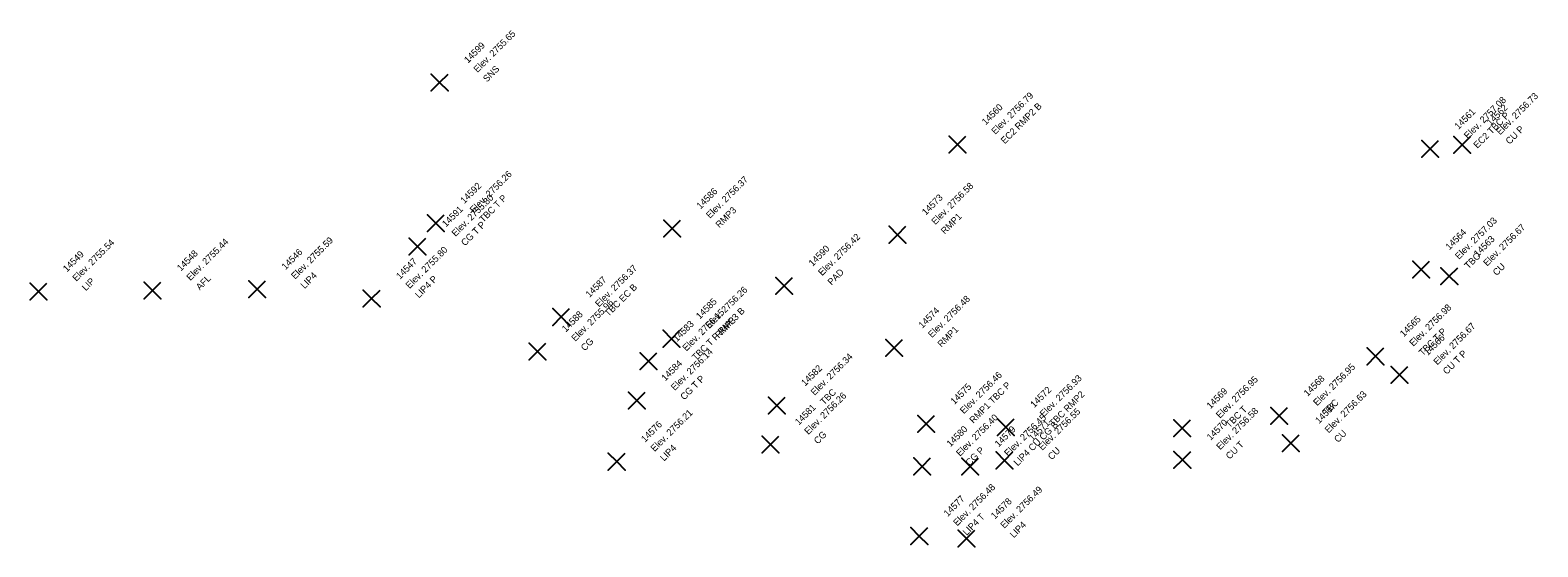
# Model space of a CAD drawing. Extents: x 2493999 to 2503109, y 700767 to 706646.
# Drawn here: x 2502322.65 to 2502349.68, y 703555.99 to 703565.25 of the extents above; entities that cross this region are included whole.
import ezdxf

# ---------------------------------------------------------------- set-up
doc = ezdxf.new("R2010")
doc.units = 0
doc.layers.add('ALG_CL_BLUE_Horiz', color=7, linetype='Continuous')
doc.layers.add('DES_SURFACE_Existing-Ground', color=7, linetype='Continuous')

msp = doc.modelspace()

# ---------------------------------------------------------------- linework, layer by layer
at = {"layer": 'ALG_CL_BLUE_Horiz'}
for points in [[(2502329.994, 703564.309), (2502329.844, 703564.459), (2502329.994, 703564.309), (2502329.844, 703564.159), (2502329.994, 703564.309), (2502330.144, 703564.159), (2502329.994, 703564.309), (2502330.144, 703564.459)], [(2502339.277, 703563.201), (2502339.127, 703563.351), (2502339.277, 703563.201), (2502339.127, 703563.051), (2502339.277, 703563.201), (2502339.427, 703563.051), (2502339.277, 703563.201), (2502339.427, 703563.351)], [(2502347.752, 703563.12), (2502347.602, 703563.27), (2502347.752, 703563.12), (2502347.602, 703562.97), (2502347.752, 703563.12), (2502347.902, 703562.97), (2502347.752, 703563.12), (2502347.902, 703563.27)], [(2502348.328, 703563.192), (2502348.178, 703563.342), (2502348.328, 703563.192), (2502348.178, 703563.042), (2502348.328, 703563.192), (2502348.478, 703563.042), (2502348.328, 703563.192), (2502348.478, 703563.342)], [(2502329.927, 703561.791), (2502329.777, 703561.941), (2502329.927, 703561.791), (2502329.777, 703561.641), (2502329.927, 703561.791), (2502330.077, 703561.641), (2502329.927, 703561.791), (2502330.077, 703561.941)], [(2502334.162, 703561.694), (2502334.012, 703561.844), (2502334.162, 703561.694), (2502334.012, 703561.544), (2502334.162, 703561.694), (2502334.312, 703561.544), (2502334.162, 703561.694), (2502334.312, 703561.844)], [(2502338.202, 703561.582), (2502338.052, 703561.732), (2502338.202, 703561.582), (2502338.052, 703561.432), (2502338.202, 703561.582), (2502338.352, 703561.432), (2502338.202, 703561.582), (2502338.352, 703561.732)], [(2502329.599, 703561.371), (2502329.449, 703561.521), (2502329.599, 703561.371), (2502329.449, 703561.221), (2502329.599, 703561.371), (2502329.749, 703561.221), (2502329.599, 703561.371), (2502329.749, 703561.521)], [(2502347.59, 703560.96), (2502347.44, 703561.11), (2502347.59, 703560.96), (2502347.44, 703560.81), (2502347.59, 703560.96), (2502347.74, 703560.81), (2502347.59, 703560.96), (2502347.74, 703561.11)], [(2502324.846, 703560.58), (2502324.696, 703560.73), (2502324.846, 703560.58), (2502324.696, 703560.43), (2502324.846, 703560.58), (2502324.996, 703560.43), (2502324.846, 703560.58), (2502324.996, 703560.73)], [(2502326.723, 703560.605), (2502326.573, 703560.755), (2502326.723, 703560.605), (2502326.573, 703560.455), (2502326.723, 703560.605), (2502326.873, 703560.455), (2502326.723, 703560.605), (2502326.873, 703560.755)], [(2502336.172, 703560.667), (2502336.022, 703560.817), (2502336.172, 703560.667), (2502336.022, 703560.517), (2502336.172, 703560.667), (2502336.322, 703560.517), (2502336.172, 703560.667), (2502336.322, 703560.817)], [(2502348.097, 703560.838), (2502347.947, 703560.988), (2502348.097, 703560.838), (2502347.947, 703560.688), (2502348.097, 703560.838), (2502348.247, 703560.688), (2502348.097, 703560.838), (2502348.247, 703560.988)], [(2502322.802, 703560.566), (2502322.652, 703560.716), (2502322.802, 703560.566), (2502322.652, 703560.416), (2502322.802, 703560.566), (2502322.952, 703560.416), (2502322.802, 703560.566), (2502322.952, 703560.716)], [(2502328.775, 703560.436), (2502328.625, 703560.586), (2502328.775, 703560.436), (2502328.625, 703560.286), (2502328.775, 703560.436), (2502328.925, 703560.286), (2502328.775, 703560.436), (2502328.925, 703560.586)], [(2502332.173, 703560.107), (2502332.023, 703560.257), (2502332.173, 703560.107), (2502332.023, 703559.957), (2502332.173, 703560.107), (2502332.323, 703559.957), (2502332.173, 703560.107), (2502332.323, 703560.257)], [(2502334.151, 703559.718), (2502334.001, 703559.868), (2502334.151, 703559.718), (2502334.001, 703559.568), (2502334.151, 703559.718), (2502334.301, 703559.568), (2502334.151, 703559.718), (2502334.301, 703559.868)], [(2502338.142, 703559.556), (2502337.992, 703559.706), (2502338.142, 703559.556), (2502337.992, 703559.406), (2502338.142, 703559.556), (2502338.292, 703559.406), (2502338.142, 703559.556), (2502338.292, 703559.706)], [(2502331.747, 703559.489), (2502331.597, 703559.639), (2502331.747, 703559.489), (2502331.597, 703559.339), (2502331.747, 703559.489), (2502331.897, 703559.339), (2502331.747, 703559.489), (2502331.897, 703559.639)], [(2502333.739, 703559.316), (2502333.589, 703559.466), (2502333.739, 703559.316), (2502333.589, 703559.166), (2502333.739, 703559.316), (2502333.889, 703559.166), (2502333.739, 703559.316), (2502333.889, 703559.466)], [(2502346.772, 703559.402), (2502346.622, 703559.552), (2502346.772, 703559.402), (2502346.622, 703559.252), (2502346.772, 703559.402), (2502346.922, 703559.252), (2502346.772, 703559.402), (2502346.922, 703559.552)], [(2502347.203, 703559.068), (2502347.053, 703559.218), (2502347.203, 703559.068), (2502347.053, 703558.918), (2502347.203, 703559.068), (2502347.353, 703558.918), (2502347.203, 703559.068), (2502347.353, 703559.218)], [(2502333.531, 703558.61), (2502333.381, 703558.76), (2502333.531, 703558.61), (2502333.381, 703558.46), (2502333.531, 703558.61), (2502333.681, 703558.46), (2502333.531, 703558.61), (2502333.681, 703558.76)], [(2502336.038, 703558.521), (2502335.888, 703558.671), (2502336.038, 703558.521), (2502335.888, 703558.371), (2502336.038, 703558.521), (2502336.188, 703558.371), (2502336.038, 703558.521), (2502336.188, 703558.671)], [(2502338.715, 703558.191), (2502338.565, 703558.341), (2502338.715, 703558.191), (2502338.565, 703558.041), (2502338.715, 703558.191), (2502338.865, 703558.041), (2502338.715, 703558.191), (2502338.865, 703558.341)], [(2502345.048, 703558.336), (2502344.898, 703558.486), (2502345.048, 703558.336), (2502344.898, 703558.186), (2502345.048, 703558.336), (2502345.198, 703558.186), (2502345.048, 703558.336), (2502345.198, 703558.486)], [(2502340.146, 703558.134), (2502339.996, 703558.284), (2502340.146, 703558.134), (2502339.996, 703557.984), (2502340.146, 703558.134), (2502340.296, 703557.984), (2502340.146, 703558.134), (2502340.296, 703558.284)], [(2502343.305, 703558.112), (2502343.155, 703558.262), (2502343.305, 703558.112), (2502343.155, 703557.962), (2502343.305, 703558.112), (2502343.455, 703557.962), (2502343.305, 703558.112), (2502343.455, 703558.262)], [(2502335.925, 703557.82), (2502335.775, 703557.97), (2502335.925, 703557.82), (2502335.775, 703557.67), (2502335.925, 703557.82), (2502336.075, 703557.67), (2502335.925, 703557.82), (2502336.075, 703557.97)], [(2502345.253, 703557.847), (2502345.103, 703557.997), (2502345.253, 703557.847), (2502345.103, 703557.697), (2502345.253, 703557.847), (2502345.403, 703557.697), (2502345.253, 703557.847), (2502345.403, 703557.997)], [(2502333.168, 703557.514), (2502333.018, 703557.664), (2502333.168, 703557.514), (2502333.018, 703557.364), (2502333.168, 703557.514), (2502333.318, 703557.364), (2502333.168, 703557.514), (2502333.318, 703557.664)], [(2502338.645, 703557.43), (2502338.495, 703557.58), (2502338.645, 703557.43), (2502338.495, 703557.28), (2502338.645, 703557.43), (2502338.795, 703557.28), (2502338.645, 703557.43), (2502338.795, 703557.58)], [(2502339.508, 703557.428), (2502339.358, 703557.578), (2502339.508, 703557.428), (2502339.358, 703557.278), (2502339.508, 703557.428), (2502339.658, 703557.278), (2502339.508, 703557.428), (2502339.658, 703557.578)], [(2502340.12, 703557.537), (2502339.97, 703557.687), (2502340.12, 703557.537), (2502339.97, 703557.387), (2502340.12, 703557.537), (2502340.27, 703557.387), (2502340.12, 703557.537), (2502340.27, 703557.687)], [(2502343.31, 703557.547), (2502343.16, 703557.697), (2502343.31, 703557.547), (2502343.16, 703557.397), (2502343.31, 703557.547), (2502343.46, 703557.397), (2502343.31, 703557.547), (2502343.46, 703557.697)], [(2502338.594, 703556.181), (2502338.444, 703556.331), (2502338.594, 703556.181), (2502338.444, 703556.031), (2502338.594, 703556.181), (2502338.744, 703556.031), (2502338.594, 703556.181), (2502338.744, 703556.331)], [(2502339.439, 703556.137), (2502339.289, 703556.287), (2502339.439, 703556.137), (2502339.289, 703555.987), (2502339.439, 703556.137), (2502339.589, 703555.987), (2502339.439, 703556.137), (2502339.589, 703556.287)]]:
    msp.add_lwpolyline(points, dxfattribs=at)

# ---------------------------------------------------------------- texts
at = {"layer": 'DES_SURFACE_Existing-Ground'}
for s, p in [('Elev. 2755.65', (2502330.673, 703564.479)), ('14599', (2502330.503, 703564.648)), ('SNS', (2502330.843, 703564.309)), ('Elev. 2756.79', (2502339.956, 703563.371)), ('Elev. 2757.08', (2502348.431, 703563.29)), ('Elev. 2756.73', (2502349.007, 703563.362)), ('14560', (2502339.786, 703563.54)), ('EC2 RMP2 B', (2502340.126, 703563.201)), ('14561', (2502348.261, 703563.459)), ('EC2 TBC P', (2502348.601, 703563.12)), ('14562', (2502348.837, 703563.531)), ('CU P', (2502349.177, 703563.192)), ('Elev. 2756.26', (2502330.606, 703561.961)), ('Elev. 2756.37', (2502334.841, 703561.864)), ('14592', (2502330.436, 703562.13)), ('14586', (2502334.671, 703562.033)), ('Elev. 2756.58', (2502338.881, 703561.752)), ('14591', (2502330.108, 703561.71)), ('Elev. 2755.80', (2502330.278, 703561.541)), ('TBC T P', (2502330.776, 703561.791)), ('14573', (2502338.711, 703561.921)), ('CG T P', (2502330.448, 703561.371)), ('RMP3', (2502335.011, 703561.694)), ('RMP1', (2502339.051, 703561.582)), ('Elev. 2757.03', (2502348.269, 703561.13)), ('Elev. 2756.42', (2502336.851, 703560.837)), ('14564', (2502348.099, 703561.299)), ('14563', (2502348.606, 703561.177)), ('Elev. 2756.67', (2502348.776, 703561.008)), ('14549', (2502323.311, 703560.905)), ('Elev. 2755.54', (2502323.481, 703560.736)), ('14548', (2502325.355, 703560.919)), ('Elev. 2755.44', (2502325.525, 703560.75)), ('14546', (2502327.232, 703560.944)), ('Elev. 2755.59', (2502327.402, 703560.775)), ('Elev. 2755.80', (2502329.454, 703560.606)), ('14590', (2502336.681, 703561.006)), ('14547', (2502329.284, 703560.775)), ('Elev. 2756.37', (2502332.852, 703560.277)), ('TBC', (2502348.439, 703560.96)), ('CU', (2502348.946, 703560.838)), ('LIP', (2502323.651, 703560.566)), ('AFL', (2502325.695, 703560.58)), ('LIP4', (2502327.572, 703560.605)), ('LIP4 P', (2502329.624, 703560.436)), ('14587', (2502332.682, 703560.446)), ('PAD', (2502337.021, 703560.667)), ('TBC EC B', (2502333.022, 703560.107)), ('Elev. 2756.26', (2502334.83, 703559.888)), ('Elev. 2756.48', (2502338.821, 703559.726)), ('14588', (2502332.256, 703559.828)), ('Elev. 2755.96', (2502332.426, 703559.659)), ('Elev. 2756.15', (2502334.418, 703559.486)), ('TBC T P RMP3 B', (2502334.588, 703559.316)), ('14585', (2502334.66, 703560.057)), ('14574', (2502338.651, 703559.895)), ('Elev. 2756.98', (2502347.451, 703559.572)), ('14583', (2502334.248, 703559.655)), ('RMP3', (2502335, 703559.718)), ('RMP1', (2502338.991, 703559.556)), ('14565', (2502347.281, 703559.741)), ('Elev. 2756.67', (2502347.882, 703559.238)), ('CG', (2502332.596, 703559.489)), ('TBC T P', (2502347.621, 703559.402)), ('14566', (2502347.712, 703559.407)), ('Elev. 2756.14', (2502334.21, 703558.78)), ('Elev. 2756.34', (2502336.717, 703558.691)), ('CU T P', (2502348.052, 703559.068)), ('14584', (2502334.04, 703558.949)), ('14582', (2502336.547, 703558.86)), ('Elev. 2756.46', (2502339.394, 703558.361)), ('Elev. 2756.95', (2502345.727, 703558.506)), ('CG T P', (2502334.38, 703558.61)), ('14575', (2502339.224, 703558.53)), ('RMP1 TBC P', (2502339.564, 703558.191)), ('14572', (2502340.655, 703558.473)), ('Elev. 2756.93', (2502340.825, 703558.304)), ('14569', (2502343.814, 703558.451)), ('Elev. 2756.95', (2502343.984, 703558.282)), ('14568', (2502345.557, 703558.675)), ('Elev. 2756.26', (2502336.604, 703557.99)), ('TBC', (2502336.887, 703558.521)), ('TBC RMP2', (2502340.995, 703558.134)), ('14567', (2502345.762, 703558.186)), ('TBC', (2502345.897, 703558.336)), ('Elev. 2756.63', (2502345.932, 703558.017)), ('Elev. 2756.21', (2502333.847, 703557.684)), ('14581', (2502336.434, 703558.159)), ('Elev. 2756.40', (2502339.324, 703557.6)), ('Elev. 2756.45', (2502340.187, 703557.598)), ('Elev. 2756.55', (2502340.799, 703557.707)), ('Elev. 2756.58', (2502343.989, 703557.717)), ('TBC T', (2502344.154, 703558.112)), ('14576', (2502333.677, 703557.853)), ('CG', (2502336.774, 703557.82)), ('14580', (2502339.154, 703557.769)), ('14579', (2502340.017, 703557.767)), ('LIP4 CU CG B', (2502340.357, 703557.428)), ('14571', (2502340.629, 703557.876)), ('14570', (2502343.819, 703557.886)), ('CU', (2502346.102, 703557.847)), ('LIP4', (2502334.017, 703557.514)), ('CG P', (2502339.494, 703557.43)), ('CU', (2502340.969, 703557.537)), ('CU T', (2502344.159, 703557.547)), ('Elev. 2756.48', (2502339.273, 703556.351)), ('Elev. 2756.49', (2502340.118, 703556.307)), ('14577', (2502339.103, 703556.52)), ('14578', (2502339.948, 703556.476)), ('LIP4 T', (2502339.443, 703556.181)), ('LIP4', (2502340.288, 703556.137))]:
    msp.add_text(s, height=0.12, rotation=45, dxfattribs=at).set_placement(p)

doc.saveas('drawing.dxf')
